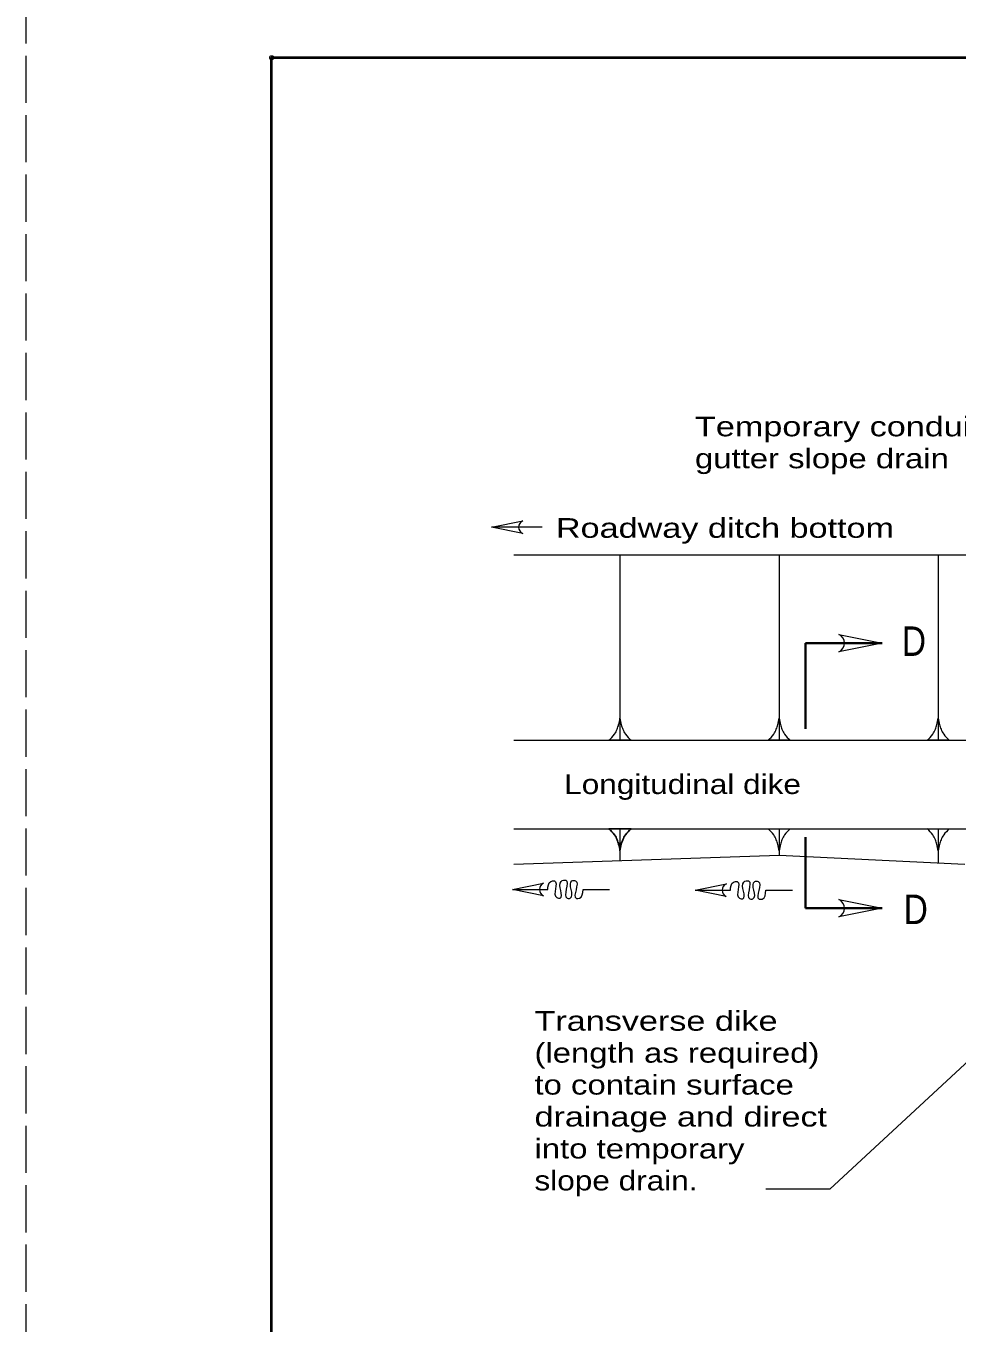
# Model space of a CAD drawing. Extents: x 1043.1 to 1101.1, y 672.4 to 716.4.
# Drawn here: x 1043.14 to 1050.72, y 683.59 to 694.15 of the extents above; entities that cross this region are included whole.
import ezdxf
from ezdxf.enums import TextEntityAlignment as Align

# ---------------------------------------------------------------- set-up
doc = ezdxf.new("R2010")
doc.units = 0
doc.header["$LTSCALE"] = 0.064
doc.header["$PDMODE"] = 32
doc.header["$PDSIZE"] = 0.032
doc.linetypes.add('LONG_DASHED', pattern=[7.5, 6, -1.5])
doc.layers.add('1', color=7, linetype='Continuous', lineweight=13)

msp = doc.modelspace()

# ---------------------------------------------------------------- linework, layer by layer
at = {"layer": '1', "lineweight": 25}
for p, q in [((1045.14425, 693.89508), (1076.64425, 693.89508)), ((1047.88975, 687.61725), (1048.06967, 687.61725))]:
    msp.add_line(p, q, dxfattribs=at)
at = {"layer": '1', "lineweight": 40}
msp.add_line((1045.14425, 693.89508), (1076.64425, 693.89508), dxfattribs=at)
msp.add_line((1045.14425, 693.89508), (1076.64425, 693.89508), dxfattribs=at)
at = {"layer": '1'}
for p, q in [((1047.34642, 690.072), (1046.93375, 690.072)), ((1047.11617, 689.848), (1055.03217, 689.848)), ((1047.97967, 689.848), (1047.97967, 688.33692)), ((1049.275, 689.848), (1049.275, 688.33692)), ((1050.57042, 689.848), (1050.57042, 688.33692)), ((1047.11617, 688.33692), (1055.0785, 688.33692)), ((1048.06967, 688.33692), (1047.88975, 688.33692)), ((1049.365, 688.33692), (1049.185, 688.33692)), ((1050.66033, 688.33692), (1050.48042, 688.33692)), ((1047.11617, 687.61725), (1051.14617, 687.61725)), ((1047.97967, 687.61725), (1047.97967, 687.35825)), ((1049.185, 687.61725), (1049.365, 687.61725)), ((1049.275, 687.61725), (1049.275, 687.4015)), ((1050.48042, 687.61725), (1050.66033, 687.61725)), ((1050.57042, 687.61725), (1050.57042, 687.33992)), ((1047.10375, 687.12217), (1047.39167, 687.12217)), ((1047.6795, 687.12217), (1047.89542, 687.12217)), ((1048.591, 687.11725), (1048.87892, 687.11675)), ((1049.16683, 687.11642), (1049.38275, 687.11617))]:
    msp.add_line(p, q, dxfattribs=at)
at = {"layer": '1', "lineweight": 35}
for p, q in [((1049.49092, 689.1285), (1050.11392, 689.1285)), ((1049.49092, 689.1285), (1049.49092, 688.43108)), ((1049.49092, 687.54892), (1049.49092, 686.96975)), ((1049.49092, 686.96975), (1050.11392, 686.96975))]:
    msp.add_line(p, q, dxfattribs=at)
at = {"layer": '1', "linetype": 'LONG_DASHED'}
msp.add_lwpolyline([(1043.14425, 672.39508), (1077.14425, 672.39508), (1077.14425, 694.39508), (1043.14425, 694.39508)], close=True, dxfattribs=at)
at = {"layer": '1', "lineweight": 25}
msp.add_lwpolyline([(1076.64425, 672.89508), (1045.14425, 672.89508), (1045.14425, 693.89508)], dxfattribs=at)
at = {"layer": '1', "lineweight": 40}
msp.add_lwpolyline([(1076.64425, 672.89508), (1045.14425, 672.89508), (1045.14425, 693.89508)], dxfattribs=at)
msp.add_lwpolyline([(1076.64425, 672.89508), (1045.14425, 672.89508), (1045.14425, 693.89508)], dxfattribs=at)
at = {"layer": '1'}
for points in [[(1047.188, 690.02108), (1046.93375, 690.072), (1047.188, 690.12292), (1047.188, 690.12275)], [(1049.75992, 689.19933), (1050.11392, 689.1285), (1049.75992, 689.05775), (1049.76, 689.05783)], [(1047.11617, 687.3295), (1049.275, 687.4015), (1050.78633, 687.3295)], [(1047.358, 687.07125), (1047.10375, 687.12217), (1047.358, 687.17308), (1047.358, 687.17275)], [(1048.84525, 687.066), (1048.591, 687.11725), (1048.84533, 687.16767), (1048.84533, 687.1675)], [(1049.75992, 687.04058), (1050.11392, 686.96975), (1049.75992, 686.899), (1049.76, 686.89908)], [(1051.44233, 686.307), (1049.68783, 684.68225), (1049.16592, 684.68225)]]:
    msp.add_lwpolyline(points, dxfattribs=at)
for centre, radius, start, end in [((1047.20863, 690.07191), 0.05488, 112.08789, 247.91402), ((1049.73127, 689.1286), 0.0764, 292.08605, 67.91218), ((1047.3787, 687.12204), 0.05488, 112.08789, 247.91402), ((1048.86596, 687.11666), 0.05488, 111.99319, 247.81932), ((1049.73127, 686.96985), 0.0764, 292.08605, 67.91218)]:
    msp.add_arc(centre, radius, start, end, dxfattribs=at)
for points in [[(1047.88975, 688.33692), (1047.93567, 688.3875), (1047.95683, 688.42708), (1047.96883, 688.4645), (1047.97967, 688.51675)], [(1047.97967, 688.51675), (1047.99042, 688.4645), (1048.0025, 688.42708), (1048.02383, 688.3875), (1048.06967, 688.33692)], [(1049.185, 688.33692), (1049.23092, 688.3875), (1049.25217, 688.42708), (1049.26425, 688.4645), (1049.275, 688.51675)], [(1049.275, 688.51675), (1049.28583, 688.4645), (1049.29792, 688.42708), (1049.31925, 688.3875), (1049.365, 688.33692)], [(1050.48042, 688.33692), (1050.52633, 688.3875), (1050.5475, 688.42708), (1050.55967, 688.4645), (1050.57042, 688.51675)], [(1050.57042, 688.51675), (1050.58125, 688.4645), (1050.59333, 688.42708), (1050.61467, 688.3875), (1050.66033, 688.33692)], [(1049.275, 687.43742), (1049.26425, 687.48967), (1049.25217, 687.52725), (1049.23092, 687.56692), (1049.185, 687.61725)], [(1049.365, 687.61725), (1049.31925, 687.56692), (1049.29792, 687.52725), (1049.28583, 687.48967), (1049.275, 687.43742)], [(1050.57042, 687.43742), (1050.55967, 687.48967), (1050.5475, 687.52725), (1050.52633, 687.56692), (1050.48042, 687.61725)], [(1050.66033, 687.61725), (1050.61467, 687.56692), (1050.59333, 687.52725), (1050.58125, 687.48967), (1050.57042, 687.43742)], [(1047.39167, 687.12217), (1047.41625, 687.18792), (1047.44633, 687.19192), (1047.46433, 687.05625), (1047.49192, 687.05317), (1047.50017, 687.18875), (1047.53842, 687.19842), (1047.55067, 687.0515), (1047.57517, 687.05225), (1047.589, 687.19292), (1047.61675, 687.19358), (1047.62575, 687.04975), (1047.65017, 687.05075), (1047.6795, 687.12217)], [(1048.87892, 687.11675), (1048.9035, 687.18242), (1048.93375, 687.18642), (1048.95142, 687.05075), (1048.97917, 687.04767), (1048.9875, 687.18325), (1049.02583, 687.19292), (1049.03783, 687.04592), (1049.06233, 687.04667), (1049.07642, 687.18708), (1049.10417, 687.18792), (1049.11292, 687.04417), (1049.13733, 687.045), (1049.16683, 687.11642)]]:
    msp.add_spline(points, degree=3, dxfattribs=at)
at = {"layer": '1', "lineweight": 25}
for points in [[(1047.97967, 687.43742), (1047.96883, 687.48967), (1047.95683, 687.52725), (1047.93567, 687.56692), (1047.88975, 687.61725)], [(1048.06967, 687.61725), (1048.02383, 687.56692), (1048.0025, 687.52725), (1047.99042, 687.48967), (1047.97967, 687.43742)]]:
    msp.add_spline(points, degree=3, dxfattribs=at)
at = {"layer": '1'}
msp.add_point((1045.14425, 693.89508), dxfattribs=at)

# ---------------------------------------------------------------- texts
for s, width, p in [('Temporary conduit or', 1.3, (1048.59017, 690.81208)), ('gutter slope drain', 1.25, (1048.59017, 690.55208)), ('Roadway ditch bottom', 1.3, (1047.45825, 689.98575)), ('Longitudinal dike', 1.2, (1047.5255, 687.89975)), ('Transverse dike', 1.3, (1047.28367, 685.97267)), ('(length as required)', 1.25, (1047.28367, 685.71267)), ('to contain surface', 1.25, (1047.28367, 685.45267)), ('drainage and direct', 1.3, (1047.28367, 685.19267)), ('into temporary', 1.25, (1047.28367, 684.93267)), ('slope drain.', 1.2, (1047.28367, 684.67267))]:
    msp.add_text(s, height=0.16, dxfattribs=dict(at, width=width)).set_placement(p)
at = {"layer": '1', "width": 0.85}
for p in [(1050.37229, 689.02442), (1050.38738, 686.841)]:
    msp.add_text('D', height=0.24, dxfattribs=at).set_placement(p, align=Align.CENTER)

doc.saveas('drawing.dxf')
